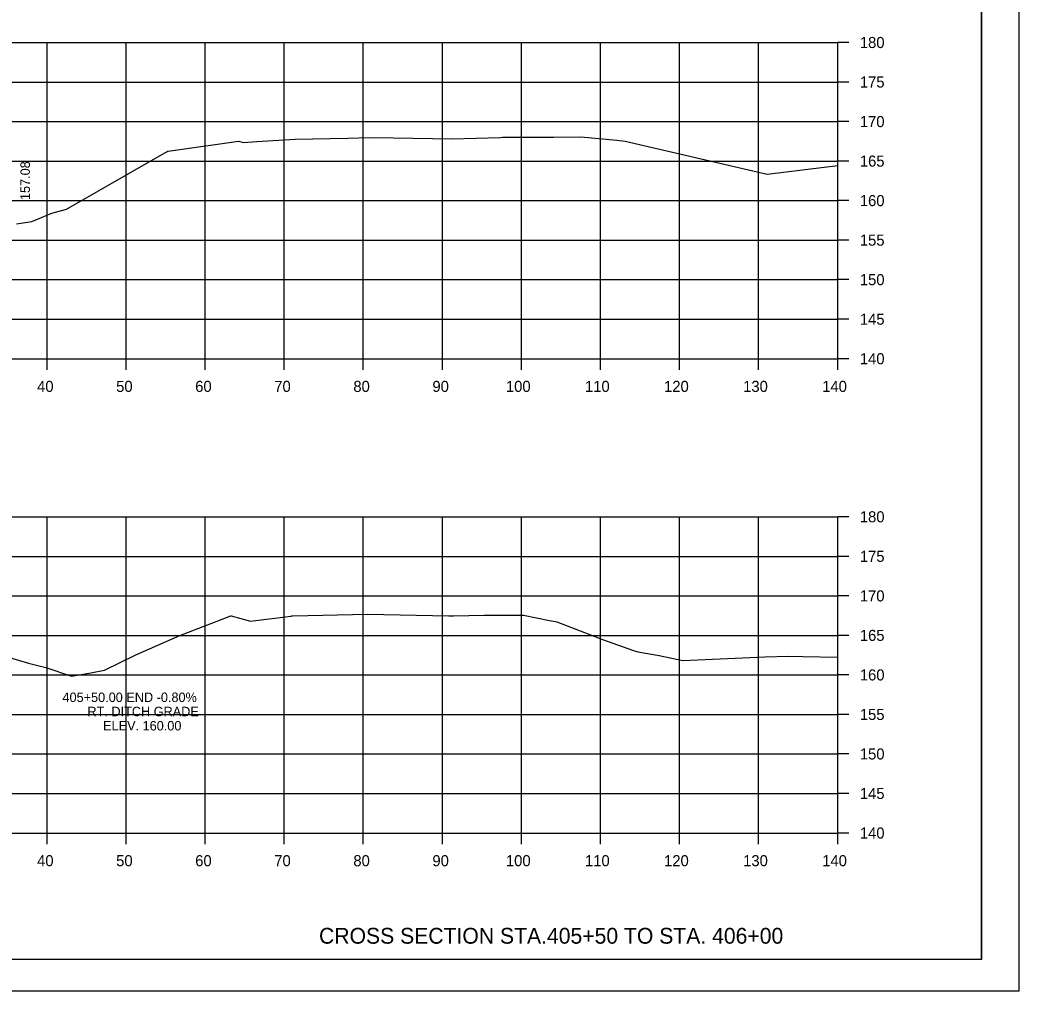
# Model space of a CAD drawing. Extents: x 1368503 to 1373085, y 379840 to 381833.
# Drawn here: x 1372958.7 to 1373085, y 380601.6 to 380724.5 of the extents above; entities that cross this region are included whole.
import ezdxf

# ---------------------------------------------------------------- set-up
doc = ezdxf.new("R2010")
doc.units = 0
for name, color, linetype in [('S_BRIDGE', 7, 'Continuous'), ('S_EDGE_PAVEMENT', 7, 'Continuous'), ('S_GRAVEL_ROAD', 7, 'Continuous'), ('S_MISC_BOUNDARY', 7, 'Continuous'), ('S_PHOTO_CENTERS', 7, 'Continuous'), ('S_PHOTO_NOTES', 7, 'Continuous'), ('S_SHOULDER', 7, 'Continuous'), ('S_TRAILS', 7, 'Continuous'), ('S_TREE', 7, 'Continuous')]:
    doc.layers.add(name, color=color, linetype=linetype)

msp = doc.modelspace()

# ---------------------------------------------------------------- linework, layer by layer
at = {"layer": 'S_BRIDGE'}
for q in [(1373080.26, 380811.09), (1372764.08, 380605.63)]:
    msp.add_line((1373080.26, 380605.63), q, dxfattribs=at)
at = {"layer": 'S_EDGE_PAVEMENT'}
for p, q in [((1373062.08, 380681.63), (1373062.08, 380721.63)), ((1373063.48, 380721.63), (1373062.08, 380721.63)), ((1373063.48, 380716.63), (1373062.08, 380716.63)), ((1373063.48, 380711.63), (1373062.08, 380711.63)), ((1373063.48, 380706.63), (1373062.08, 380706.63)), ((1373063.48, 380701.63), (1373062.08, 380701.63)), ((1373063.48, 380696.63), (1373062.08, 380696.63)), ((1373063.48, 380691.63), (1373062.08, 380691.63)), ((1373063.48, 380686.63), (1373062.08, 380686.63)), ((1372782.08, 380681.63), (1373062.08, 380681.63)), ((1372962.08, 380680.23), (1372962.08, 380681.63)), ((1372972.08, 380680.23), (1372972.08, 380681.63)), ((1372982.08, 380680.23), (1372982.08, 380681.63)), ((1372992.08, 380680.23), (1372992.08, 380681.63)), ((1373002.08, 380680.23), (1373002.08, 380681.63)), ((1373012.08, 380680.23), (1373012.08, 380681.63)), ((1373022.08, 380680.23), (1373022.08, 380681.63)), ((1373032.08, 380680.23), (1373032.08, 380681.63)), ((1373042.08, 380680.23), (1373042.08, 380681.63)), ((1373052.08, 380680.23), (1373052.08, 380681.63)), ((1373062.08, 380680.23), (1373062.08, 380681.63)), ((1373063.48, 380681.63), (1373062.08, 380681.63)), ((1373062.08, 380621.63), (1373062.08, 380661.63)), ((1373063.48, 380661.63), (1373062.08, 380661.63)), ((1373063.48, 380656.63), (1373062.08, 380656.63)), ((1373063.48, 380651.63), (1373062.08, 380651.63)), ((1373063.48, 380646.63), (1373062.08, 380646.63)), ((1373063.48, 380641.63), (1373062.08, 380641.63)), ((1373063.48, 380636.63), (1373062.08, 380636.63)), ((1373063.48, 380631.63), (1373062.08, 380631.63)), ((1373063.48, 380626.63), (1373062.08, 380626.63)), ((1372782.08, 380621.63), (1373062.08, 380621.63)), ((1372962.08, 380620.23), (1372962.08, 380621.63)), ((1372972.08, 380620.23), (1372972.08, 380621.63)), ((1372982.08, 380620.23), (1372982.08, 380621.63)), ((1372992.08, 380620.23), (1372992.08, 380621.63)), ((1373002.08, 380620.23), (1373002.08, 380621.63)), ((1373012.08, 380620.23), (1373012.08, 380621.63)), ((1373022.08, 380620.23), (1373022.08, 380621.63)), ((1373032.08, 380620.23), (1373032.08, 380621.63)), ((1373042.08, 380620.23), (1373042.08, 380621.63)), ((1373052.08, 380620.23), (1373052.08, 380621.63)), ((1373062.08, 380620.23), (1373062.08, 380621.63)), ((1373063.48, 380621.63), (1373062.08, 380621.63))]:
    msp.add_line(p, q, dxfattribs=at)
at = {"layer": 'S_MISC_BOUNDARY'}
for points in [[(1372958.21, 380698.7), (1372960.17, 380698.99), (1372962.68, 380700.06), (1372964.52, 380700.56), (1372976.96, 380707.69), (1372977.3, 380707.86), (1372977.32, 380707.87), (1372977.33, 380707.85), (1372977.35, 380707.89), (1372977.4, 380707.9), (1372986.29, 380709.14), (1372986.92, 380708.99), (1372988.62, 380709.12), (1372993.46, 380709.4), (1373000.14, 380709.54), (1373002.88, 380709.6), (1373005.91, 380709.55), (1373013.29, 380709.43), (1373019.44, 380709.63), (1373019.67, 380709.64), (1373020.02, 380709.65), (1373026.15, 380709.66), (1373029.61, 380709.71), (1373034.15, 380709.26), (1373035.18, 380709.14), (1373053.18, 380704.97), (1373062.08, 380706.08)], [(1372955.01, 380644.49), (1372959.73, 380643.1), (1372961.93, 380642.57), (1372965.16, 380641.46), (1372967.63, 380641.89), (1372969.33, 380642.24), (1372973.31, 380644.19), (1372978.87, 380646.62), (1372985.33, 380649.1), (1372985.36, 380649.11), (1372985.38, 380649.11), (1372987.8, 380648.43), (1372992.91, 380649.08), (1372993.03, 380649.09), (1372993.17, 380649.1), (1373002.61, 380649.3), (1373012.89, 380649.12), (1373013.16, 380649.12), (1373013.5, 380649.12), (1373017.36, 380649.19), (1373019.35, 380649.18), (1373022.32, 380649.19), (1373025.61, 380648.51), (1373026.38, 380648.38), (1373026.55, 380648.34), (1373032.48, 380646.05), (1373036.13, 380644.77), (1373036.8, 380644.57), (1373039.48, 380644.07), (1373042.49, 380643.47), (1373052.88, 380643.9), (1373055.87, 380644), (1373057.65, 380643.97), (1373062.08, 380643.89)]]:
    msp.add_lwpolyline(points, dxfattribs=at)
at = {"layer": 'S_PHOTO_CENTERS'}
for p, q in [((1372782.08, 380721.63), (1373062.08, 380721.63)), ((1372962.08, 380681.63), (1372962.08, 380721.63)), ((1372972.08, 380681.63), (1372972.08, 380721.63)), ((1372982.08, 380681.63), (1372982.08, 380721.63)), ((1372992.08, 380681.63), (1372992.08, 380721.63)), ((1373002.08, 380681.63), (1373002.08, 380721.63)), ((1373012.08, 380681.63), (1373012.08, 380721.63)), ((1373022.08, 380681.63), (1373022.08, 380721.63)), ((1373032.08, 380681.63), (1373032.08, 380721.63)), ((1373042.08, 380681.63), (1373042.08, 380721.63)), ((1373052.08, 380681.63), (1373052.08, 380721.63)), ((1373062.08, 380681.63), (1373062.08, 380721.63)), ((1372782.08, 380716.63), (1373062.08, 380716.63)), ((1372782.08, 380711.63), (1373062.08, 380711.63)), ((1372782.08, 380706.63), (1373062.08, 380706.63)), ((1372782.08, 380701.63), (1373062.08, 380701.63)), ((1372782.08, 380696.63), (1373062.08, 380696.63)), ((1372782.08, 380691.63), (1373062.08, 380691.63)), ((1372782.08, 380686.63), (1373062.08, 380686.63)), ((1372782.08, 380681.63), (1373062.08, 380681.63)), ((1372782.08, 380661.63), (1373062.08, 380661.63)), ((1372962.08, 380621.63), (1372962.08, 380661.63)), ((1372972.08, 380621.63), (1372972.08, 380661.63)), ((1372982.08, 380621.63), (1372982.08, 380661.63)), ((1372992.08, 380621.63), (1372992.08, 380661.63)), ((1373002.08, 380621.63), (1373002.08, 380661.63)), ((1373012.08, 380621.63), (1373012.08, 380661.63)), ((1373022.08, 380621.63), (1373022.08, 380661.63)), ((1373032.08, 380621.63), (1373032.08, 380661.63)), ((1373042.08, 380621.63), (1373042.08, 380661.63)), ((1373052.08, 380621.63), (1373052.08, 380661.63)), ((1373062.08, 380621.63), (1373062.08, 380661.63)), ((1372782.08, 380656.63), (1373062.08, 380656.63)), ((1372782.08, 380651.63), (1373062.08, 380651.63)), ((1372782.08, 380646.63), (1373062.08, 380646.63)), ((1372782.08, 380641.63), (1373062.08, 380641.63)), ((1372782.08, 380636.63), (1373062.08, 380636.63)), ((1372782.08, 380631.63), (1373062.08, 380631.63)), ((1372782.08, 380626.63), (1373062.08, 380626.63)), ((1372782.08, 380621.63), (1373062.08, 380621.63))]:
    msp.add_line(p, q, dxfattribs=at)
at = {"layer": 'S_PHOTO_NOTES'}
msp.add_line((1372751.68, 380601.65), (1373085.01, 380601.65), dxfattribs=at)
for points in [[(1372751.67, 380814.98), (1373085.01, 380814.98), (1373085.01, 380601.64), (1372751.67, 380601.64)], [(1372998, 380811.09), (1372998, 380801.21), (1373033.73, 380801.21), (1373033.73, 380798.29), (1373056.93, 380798.29), (1373056.93, 380773.95), (1373080.26, 380773.95), (1373080.26, 380605.63), (1372764.08, 380605.63), (1372764.08, 380811.09)]]:
    msp.add_lwpolyline(points, close=True, dxfattribs=at)

# ---------------------------------------------------------------- texts
at = {"layer": 'S_GRAVEL_ROAD'}
for s, p in [('405+50.00 END -0.80%', (1372964.03, 380638.2)), ('RT. DITCH GRADE', (1372967.19, 380636.4)), ('ELEV. 160.00', (1372969.17, 380634.6))]:
    msp.add_text(s, height=1.2, dxfattribs=at).set_placement(p)
at = {"layer": 'S_SHOULDER'}
msp.add_text('157.08', height=1.2, rotation=90, dxfattribs=at).set_placement((1372959.91, 380701.7))
at = {"layer": 'S_TRAILS'}
for s, p in [('180', (1373064.88, 380720.93)), ('175', (1373064.88, 380715.93)), ('170', (1373064.88, 380710.93)), ('165', (1373064.88, 380705.93)), ('160', (1373064.88, 380700.93)), ('155', (1373064.88, 380695.93)), ('150', (1373064.88, 380690.93)), ('145', (1373064.88, 380685.93)), ('140', (1373064.88, 380680.93)), ('40', (1372960.82, 380677.43)), ('50', (1372970.82, 380677.43)), ('60', (1372980.82, 380677.43)), ('70', (1372990.82, 380677.43)), ('80', (1373000.82, 380677.43)), ('90', (1373010.82, 380677.43)), ('100', (1373020.12, 380677.43)), ('110', (1373030.12, 380677.43)), ('120', (1373040.12, 380677.43)), ('130', (1373050.12, 380677.43)), ('140', (1373060.12, 380677.43)), ('180', (1373064.88, 380660.93)), ('175', (1373064.88, 380655.93)), ('170', (1373064.88, 380650.93)), ('165', (1373064.88, 380645.93)), ('160', (1373064.88, 380640.93)), ('155', (1373064.88, 380635.93)), ('150', (1373064.88, 380630.93)), ('145', (1373064.88, 380625.93)), ('140', (1373064.88, 380620.93)), ('40', (1372960.82, 380617.43)), ('50', (1372970.82, 380617.43)), ('60', (1372980.82, 380617.43)), ('70', (1372990.82, 380617.43)), ('80', (1373000.82, 380617.43)), ('90', (1373010.82, 380617.43)), ('100', (1373020.12, 380617.43)), ('110', (1373030.12, 380617.43)), ('120', (1373040.12, 380617.43)), ('130', (1373050.12, 380617.43)), ('140', (1373060.12, 380617.43))]:
    msp.add_text(s, height=1.4, dxfattribs=at).set_placement(p)
at = {"layer": 'S_TREE'}
msp.add_text('CROSS SECTION STA.405+50 TO STA. 406+00', height=2, dxfattribs=at).set_placement((1372996.48, 380607.63))

doc.saveas('drawing.dxf')
